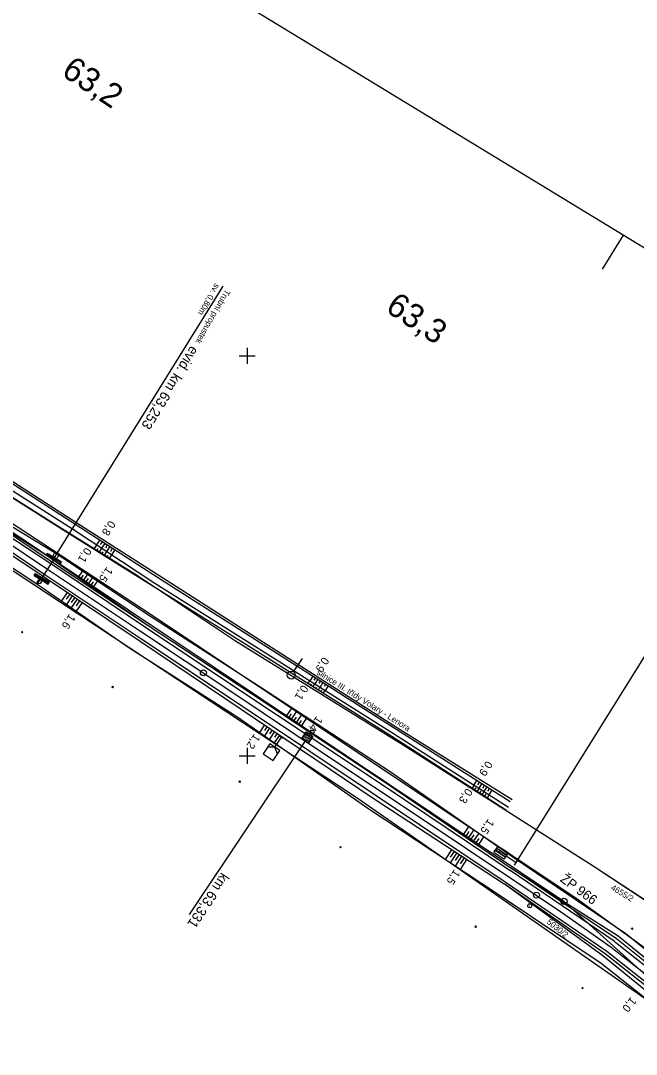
# Model space of a CAD drawing. Extents: x -804899 to -803847, y -1165742 to -1164942.
# Drawn here: x -804356.6 to -804202.8, y -1165474.6 to -1165216.2 of the extents above; entities that cross this region are included whole.
import ezdxf

# ---------------------------------------------------------------- set-up
doc = ezdxf.new("R2010")
doc.units = 0
for name, color, linetype in [('0381KM061-064P - Vrstva 1', 7, 'Continuous'), ('0381KM061-064P - Vrstva 13', 7, 'Continuous'), ('0381KM061-064P - Vrstva 17', 7, 'Continuous'), ('0381KM061-064P - Vrstva 19', 7, 'Continuous'), ('0381KM061-064P - Vrstva 27', 7, 'Continuous'), ('0381KM061-064P - Vrstva 3', 7, 'Continuous'), ('0381KM061-064P - Vrstva 36', 7, 'Continuous'), ('0381KM061-064P - Vrstva 4', 7, 'Continuous'), ('0381KM061-064P - Vrstva 48', 7, 'Continuous'), ('0381KM061-064P - Vrstva 49', 7, 'Continuous'), ('0381KM061-064P - Vrstva 51', 7, 'Continuous'), ('0381KM061-064P - Vrstva 55', 7, 'Continuous'), ('0381KM061-064P - Vrstva 57', 7, 'Continuous'), ('0381KM061-064P - Vrstva 7', 7, 'Continuous'), ('0381KM061-064P - Vrstva 8', 7, 'Continuous'), ('formát', 7, 'Continuous'), ('hran DP - hran DP', 7, 'Continuous'), ('krizky_1000 - Vrstva 1', 7, 'Continuous'), ('vyt_sit - polygon', 7, 'Continuous'), ('vyt_sit - stávající', 7, 'Continuous')]:
    doc.layers.add(name, color=color, linetype=linetype)

msp = doc.modelspace()

# ---------------------------------------------------------------- linework, layer by layer
at = {"layer": '0381KM061-064P - Vrstva 1'}
for points in [[(-804619.36, -1165173.74), (-804594.78, -1165190.05), (-804577, -1165201.91), (-804561.16, -1165212.47), (-804538.32, -1165227.67), (-804515.3, -1165243.02), (-804489.41, -1165260.27), (-804477.81, -1165268), (-804447.6, -1165288.14), (-804422.03, -1165305.2), (-804398.19, -1165321.09), (-804394.23, -1165323.73), (-804371.85, -1165338.65), (-804349.9, -1165353.29), (-804326.64, -1165368.8), (-804303.84, -1165384.01), (-804280.33, -1165399.7), (-804257.04, -1165415.23), (-804233.85, -1165430.69)], [(-804233.85, -1165430.69), (-804221.71, -1165438.86), (-804209.06, -1165447.77)], [(-804209.06, -1165447.77), (-804189.15, -1165463.4), (-804170.34, -1165480.54), (-804149.35, -1165503.13), (-804134.27, -1165522.21), (-804123.44, -1165537.79)]]:
    msp.add_lwpolyline(points, dxfattribs=at)
at = {"layer": '0381KM061-064P - Vrstva 13'}
for points in [[(-804348.53, -1165350.16), (-804348.11, -1165349.19), (-804347.55, -1165349.48)], [(-804347.71, -1165350.75), (-804347.06, -1165350.02), (-804347.55, -1165349.48)], [(-804351.94, -1165355.72), (-804352.52, -1165356.42), (-804352.55, -1165356.96)], [(-804351.23, -1165356.15), (-804351.73, -1165356.92), (-804352.55, -1165356.96)]]:
    msp.add_lwpolyline(points, dxfattribs=at)
for centre, major_axis, ratio, start_param, end_param in [((-804348.06, -1165350.36), (0.502, -0.373), 0.294364, 3.805363, 5.70381), ((-804351.59, -1165355.94), (-0.372, 0.23), 0.069899, 3.50752, 6.025727)]:
    msp.add_ellipse(centre, major_axis=major_axis, ratio=ratio, start_param=start_param, end_param=end_param, dxfattribs=at)
at = {"layer": '0381KM061-064P - Vrstva 17'}
for points in [[(-804349.85, -1165349.62), (-804346.55, -1165351.67)], [(-804349.69, -1165356.94), (-804352.99, -1165354.74)]]:
    msp.add_lwpolyline(points, dxfattribs=at)
at = {"layer": '0381KM061-064P - Vrstva 19'}
for p, q in [((-804348.23, -1165350.54), (-804306.04, -1165282.63)), ((-804348.12, -1165350.55), (-804351.58, -1165355.92))]:
    msp.add_line(p, q, dxfattribs=at)
for points in [[(-804350.13, -1165349.85), (-804349.96, -1165349.4), (-804349.94, -1165349.53)], [(-804346.52, -1165351.56), (-804349.94, -1165349.53), (-804350.13, -1165349.85), (-804346.84, -1165352.14), (-804346.52, -1165351.56)], [(-804349.96, -1165349.4), (-804348.53, -1165350.16)], [(-804346.41, -1165351.59), (-804347.71, -1165350.75)], [(-804346.84, -1165352.14), (-804346.41, -1165351.59), (-804346.52, -1165351.56)], [(-804353.14, -1165354.84), (-804353.21, -1165354.88), (-804352.95, -1165354.5)], [(-804353.14, -1165354.84), (-804349.82, -1165357.01), (-804349.52, -1165356.59), (-804352.95, -1165354.5), (-804353.14, -1165354.84)], [(-804353.21, -1165354.88), (-804351.94, -1165355.72)], [(-804349.84, -1165357.12), (-804351.23, -1165356.15)], [(-804349.52, -1165356.59), (-804349.84, -1165357.12), (-804349.82, -1165357.01)]]:
    msp.add_lwpolyline(points, dxfattribs=at)
for centre, major_axis, ratio, start_param, end_param in [((-804348.14, -1165350.46), (-0.469, 0.338), 0.066779, 5.748415, 9.878714), ((-804348.06, -1165350.36), (0.502, -0.373), 0.294364, 3.805363, 5.70381), ((-804351.59, -1165355.96), (-0.405, 0.253), 0.126448, 5.826099, 9.990944), ((-804351.59, -1165355.94), (-0.372, 0.23), 0.069899, 3.50752, 6.025727)]:
    msp.add_ellipse(centre, major_axis=major_axis, ratio=ratio, start_param=start_param, end_param=end_param, dxfattribs=at)
at = {"layer": '0381KM061-064P - Vrstva 27'}
msp.add_line((-804283.87, -1165394.04), (-804283.77, -1165394.04), dxfattribs=at)
msp.add_circle((-804283.82, -1165394.04), 0.5, dxfattribs=at)
at = {"layer": '0381KM061-064P - Vrstva 3'}
for p, q in [((-804283.6, -1165395.11), (-804286.38, -1165395.66)), ((-804284.05, -1165394.82), (-804286.08, -1165395.22)), ((-804283.9, -1165395.55), (-804285.94, -1165395.96)), ((-804284.49, -1165394.52), (-804285.79, -1165394.78)), ((-804284.93, -1165394.23), (-804285.5, -1165394.34)), ((-804284.19, -1165395.99), (-804285.5, -1165396.25)), ((-804285.55, -1165396.22), (-804314.54, -1165439.64)), ((-804284.49, -1165396.43), (-804285.06, -1165396.55))]:
    msp.add_line(p, q, dxfattribs=at)
msp.add_lwpolyline([(-804284.72, -1165396.77), (-804286.38, -1165395.66), (-804285.27, -1165394), (-804283.6, -1165395.11)], close=True, dxfattribs=at)
at = {"layer": '0381KM061-064P - Vrstva 36'}
for p, q in [((-804288.43, -1165378.96), (-804286.21, -1165375.63)), ((-804288.99, -1165379.79), (-804288.99, -1165379.79))]:
    msp.add_line(p, q, dxfattribs=at)
msp.add_circle((-804288.99, -1165379.79), 1, dxfattribs=at)
at = {"layer": '0381KM061-064P - Vrstva 4'}
for points in [[(-804755.73, -1165115.93), (-804748.17, -1165116.91), (-804721.25, -1165123.25), (-804698.66, -1165130.22), (-804681.33, -1165136.99), (-804671.47, -1165141.65), (-804648.84, -1165153.36), (-804638.11, -1165160.03), (-804624.48, -1165168.7), (-804602.56, -1165183.07), (-804574.47, -1165201.72), (-804542.72, -1165222.84), (-804507.36, -1165246.55), (-804477.08, -1165266.82), (-804448.75, -1165285.88), (-804421.18, -1165304.15), (-804392.89, -1165323.09), (-804369.85, -1165338.37), (-804348.86, -1165352.04), (-804325.13, -1165367.98), (-804299.32, -1165385.27), (-804266.05, -1165407.31), (-804234.28, -1165428.6)], [(-804755.73, -1165115.93), (-804748.03, -1165116.49), (-804721.05, -1165122.36), (-804698.44, -1165129.77), (-804680.98, -1165136.5), (-804671.21, -1165140.89), (-804648.42, -1165152.46), (-804637.55, -1165159.43), (-804624.04, -1165168.29), (-804602.25, -1165182.38), (-804573.74, -1165201.2), (-804542.46, -1165222.56), (-804507.06, -1165246.03), (-804476.47, -1165266.24), (-804448.31, -1165285.08), (-804421.02, -1165303.1), (-804392.59, -1165322.59), (-804369.41, -1165337.65), (-804348.68, -1165351.59), (-804324.76, -1165367.42), (-804298.9, -1165384.42), (-804265.65, -1165406.5), (-804234.05, -1165428.04)], [(-804626.64, -1165171.43), (-804605.18, -1165186.34), (-804576.91, -1165204.69), (-804544.69, -1165226.09), (-804509.35, -1165249.3), (-804478.87, -1165269.77), (-804450.06, -1165288.98), (-804422.82, -1165307.11), (-804394.42, -1165325.66), (-804371.77, -1165341.24), (-804350.46, -1165355.38), (-804326.73, -1165371.34), (-804301.47, -1165388.34), (-804268.3, -1165410.72), (-804235.74, -1165432.01)], [(-804576.36, -1165204.15), (-804544.19, -1165225.52), (-804508.95, -1165249), (-804478.52, -1165269.18), (-804449.67, -1165288.56), (-804422.62, -1165306.58), (-804394.22, -1165325.33), (-804371.37, -1165340.61), (-804350.54, -1165354.66), (-804326.31, -1165370.81), (-804300.9, -1165387.72), (-804267.8, -1165409.92), (-804235.52, -1165431.44)], [(-804208.29, -1165446.31), (-804234.28, -1165428.6)], [(-804207.68, -1165445.74), (-804234.05, -1165428.04)], [(-804210.55, -1165449.47), (-804235.74, -1165432.01)], [(-804235.52, -1165431.44), (-804210.13, -1165448.78)], [(-804208.29, -1165446.31), (-804188.04, -1165462.27), (-804167.24, -1165481.51), (-804148.09, -1165502.16), (-804133.09, -1165521.07), (-804122.59, -1165536.38)], [(-804149.78, -1165499.19), (-804150.31, -1165498.25), (-804166.3, -1165480.67), (-804187.69, -1165461.71), (-804207.68, -1165445.74)], [(-804153.11, -1165502.1), (-804153.8, -1165501.49), (-804170.44, -1165484.31), (-804190.7, -1165465.14), (-804210.55, -1165449.47)], [(-804210.13, -1165448.78), (-804190.15, -1165464.6), (-804169.52, -1165483.48), (-804150.26, -1165504.33), (-804135.4, -1165523.19), (-804124.45, -1165539.02), (-804124.32, -1165539.22)]]:
    msp.add_lwpolyline(points, dxfattribs=at)
at = {"layer": '0381KM061-064P - Vrstva 48'}
for p, q in [((-804337.56, -1165347.25), (-804336.79, -1165346.06)), ((-804336.62, -1165347.19), (-804336.16, -1165346.47)), ((-804336.3, -1165348.08), (-804335.53, -1165346.88)), ((-804338.21, -1165348.31), (-804337.55, -1165347.26)), ((-804337.57, -1165348.71), (-804337.25, -1165348.19)), ((-804336.93, -1165349.11), (-804336.29, -1165348.08)), ((-804336.3, -1165349.51), (-804335.98, -1165349)), ((-804335.66, -1165349.9), (-804335.04, -1165348.91)), ((-804335.36, -1165348.01), (-804334.9, -1165347.28)), ((-804335.05, -1165348.91), (-804334.27, -1165347.69)), ((-804334.11, -1165348.83), (-804333.64, -1165348.1)), ((-804333.8, -1165349.73), (-804333.01, -1165348.51)), ((-804335.03, -1165350.3), (-804334.72, -1165349.81)), ((-804334.39, -1165350.7), (-804333.79, -1165349.74)), ((-804341.15, -1165353.74), (-804342.25, -1165355.32)), ((-804340.97, -1165354.79), (-804341.63, -1165355.74)), ((-804339.9, -1165354.57), (-804341.01, -1165356.17)), ((-804339.73, -1165355.63), (-804340.4, -1165356.6)), ((-804338.66, -1165355.4), (-804339.78, -1165357.02)), ((-804338.48, -1165356.47), (-804339.16, -1165357.45)), ((-804337.41, -1165356.23), (-804338.55, -1165357.88)), ((-804346.34, -1165361.27), (-804344.9, -1165359.12)), ((-804345.15, -1165360.83), (-804344.27, -1165359.54)), ((-804345.11, -1165362.12), (-804343.65, -1165359.96)), ((-804343.91, -1165361.68), (-804343.03, -1165360.37)), ((-804343.88, -1165362.98), (-804342.41, -1165360.79)), ((-804342.67, -1165362.53), (-804341.79, -1165361.21)), ((-804342.64, -1165363.83), (-804341.16, -1165361.63)), ((-804283.59, -1165380.05), (-804284.34, -1165381.22)), ((-804282.96, -1165380.46), (-804283.33, -1165381.04)), ((-804284.75, -1165381.87), (-804284.34, -1165381.22)), ((-804284.11, -1165382.27), (-804283.91, -1165381.95)), ((-804283.48, -1165382.67), (-804283.07, -1165382.02)), ((-804282.33, -1165380.86), (-804283.07, -1165382.02)), ((-804282.85, -1165383.07), (-804282.64, -1165382.75)), ((-804282.21, -1165383.47), (-804281.81, -1165382.82)), ((-804281.7, -1165381.26), (-804282.07, -1165381.84)), ((-804281.06, -1165381.67), (-804281.8, -1165382.82)), ((-804280.43, -1165382.07), (-804280.8, -1165382.65)), ((-804279.8, -1165382.47), (-804280.54, -1165383.63)), ((-804281.58, -1165383.87), (-804281.37, -1165383.55)), ((-804280.94, -1165384.27), (-804280.54, -1165383.62)), ((-804290.26, -1165390.16), (-804288.8, -1165387.95)), ((-804289.64, -1165390.57), (-804288.9, -1165389.46)), ((-804289.01, -1165390.98), (-804287.54, -1165388.76)), ((-804288.39, -1165391.4), (-804287.65, -1165390.29)), ((-804287.76, -1165391.81), (-804286.28, -1165389.58)), ((-804286.51, -1165392.64), (-804285.02, -1165390.4)), ((-804295.65, -1165392.27), (-804296.91, -1165394.13)), ((-804294.41, -1165393.1), (-804295.68, -1165394.99)), ((-804295.03, -1165392.69), (-804295.66, -1165393.62)), ((-804293.79, -1165393.53), (-804294.43, -1165394.47)), ((-804287.14, -1165392.23), (-804286.4, -1165391.11)), ((-804293.17, -1165393.94), (-804294.45, -1165395.85)), ((-804291.92, -1165394.78), (-804293.22, -1165396.71)), ((-804292.54, -1165394.36), (-804293.19, -1165395.32)), ((-804243.31, -1165407.27), (-804242.59, -1165406.14)), ((-804243.31, -1165407.27), (-804243.8, -1165408.03)), ((-804242.88, -1165407.98), (-804243.17, -1165408.43)), ((-804242.05, -1165408.07), (-804242.54, -1165408.84)), ((-804242.39, -1165407.22), (-804241.96, -1165406.54)), ((-804242.05, -1165408.07), (-804241.33, -1165406.94)), ((-804241.61, -1165408.79), (-804241.91, -1165409.25)), ((-804240.78, -1165408.88), (-804241.29, -1165409.66)), ((-804241.13, -1165408.02), (-804240.69, -1165407.34)), ((-804240.78, -1165408.88), (-804240.06, -1165407.74)), ((-804239.86, -1165408.83), (-804239.43, -1165408.15)), ((-804239.52, -1165409.69), (-804238.8, -1165408.55)), ((-804240.35, -1165409.6), (-804240.66, -1165410.06)), ((-804239.52, -1165409.69), (-804240.03, -1165410.47)), ((-804244.59, -1165417.6), (-804246.1, -1165419.82)), ((-804244.58, -1165418.91), (-804245.48, -1165420.24)), ((-804243.36, -1165418.45), (-804244.86, -1165420.66)), ((-804242.13, -1165419.31), (-804243.62, -1165421.51)), ((-804243.34, -1165419.76), (-804244.24, -1165421.09)), ((-804242.11, -1165420.61), (-804243.01, -1165421.93)), ((-804240.9, -1165420.17), (-804242.39, -1165422.35)), ((-804250.43, -1165425.88), (-804248.84, -1165423.45)), ((-804249.18, -1165426.71), (-804247.58, -1165424.27)), ((-804249.17, -1165425.32), (-804248.21, -1165423.85)), ((-804247.93, -1165427.54), (-804246.33, -1165425.09)), ((-804247.91, -1165426.15), (-804246.95, -1165424.68)), ((-804246.68, -1165428.37), (-804245.07, -1165425.91)), ((-804246.66, -1165426.97), (-804245.7, -1165425.5))]:
    msp.add_line(p, q, dxfattribs=at)
at = {"layer": '0381KM061-064P - Vrstva 49'}
for p, q in [((-804356.09, -1165369.23), (-804356.44, -1165368.87)), ((-804356.09, -1165368.87), (-804356.44, -1165369.23)), ((-804333.45, -1165382.97), (-804333.81, -1165382.62)), ((-804333.45, -1165382.62), (-804333.81, -1165382.97)), ((-804301.7, -1165406.66), (-804302.06, -1165406.31)), ((-804301.7, -1165406.31), (-804302.06, -1165406.66)), ((-804276.5, -1165422.97), (-804276.85, -1165422.62)), ((-804276.5, -1165422.62), (-804276.85, -1165422.97)), ((-804242.71, -1165442.85), (-804243.07, -1165442.5)), ((-804242.71, -1165442.5), (-804243.07, -1165442.85)), ((-804204.05, -1165443.18), (-804203.56, -1165443.07)), ((-804203.86, -1165442.88), (-804203.75, -1165443.37)), ((-804216.05, -1165458.22), (-804216.41, -1165457.87)), ((-804216.05, -1165457.87), (-804216.41, -1165458.22))]:
    msp.add_line(p, q, dxfattribs=at)
for points in [[(-804668.09, -1165135.13), (-804646.08, -1165148.91), (-804635.34, -1165155.79), (-804621.98, -1165164.4), (-804599.68, -1165178.86), (-804570.23, -1165197.63), (-804539.04, -1165217.4), (-804503.79, -1165239.32), (-804473.21, -1165259.25), (-804445.02, -1165277.37), (-804416.3, -1165295.6), (-804385.23, -1165314.87), (-804342.84, -1165342.16), (-804322.16, -1165355.5), (-804292.15, -1165374.6), (-804262.58, -1165393.44), (-804234.25, -1165411.43)], [(-804668.53, -1165136.56), (-804646.51, -1165150.38), (-804635.75, -1165157.19), (-804622.88, -1165165.28), (-804600.74, -1165180), (-804571.06, -1165199.05), (-804539.91, -1165219.23), (-804504.85, -1165241.38), (-804474.07, -1165260.59), (-804445.75, -1165278.86), (-804417.38, -1165297.08), (-804386.13, -1165316.29), (-804343.68, -1165343.22), (-804323.05, -1165356.81), (-804293.41, -1165375.48), (-804263.45, -1165394.43), (-804234.68, -1165412.78)], [(-804576.91, -1165204.69), (-804544.69, -1165226.09), (-804509.35, -1165249.3), (-804478.87, -1165269.77), (-804450.06, -1165288.98), (-804422.82, -1165307.11), (-804394.42, -1165325.66), (-804371.77, -1165341.24), (-804350.46, -1165355.38), (-804326.73, -1165371.34), (-804301.47, -1165388.34), (-804268.3, -1165410.72), (-804235.74, -1165432.01)], [(-804474.97, -1165261.14), (-804446.16, -1165279.93), (-804417.55, -1165297.62), (-804371.56, -1165327.37), (-804344.89, -1165344.14), (-804323.3, -1165357.63), (-804293.83, -1165376.15), (-804263.84, -1165395.04), (-804235.23, -1165413.58)], [(-804475.98, -1165263.3), (-804448.01, -1165281.64), (-804419.88, -1165300.43), (-804390.2, -1165320.54), (-804368.79, -1165336.61), (-804347.55, -1165349.48), (-804323.92, -1165365.2), (-804298.45, -1165381.67), (-804264.49, -1165403.75), (-804232.5, -1165426.01)], [(-804424.02, -1165310.32), (-804397.08, -1165327.6), (-804372.3, -1165344.03), (-804352.55, -1165356.96), (-804329.59, -1165372.88)], [(-804369.41, -1165337.65), (-804350.13, -1165349.85)], [(-804348.53, -1165350.16), (-804349.96, -1165349.4), (-804350.13, -1165349.85)], [(-804348.12, -1165350.55), (-804347.55, -1165349.48)], [(-804346.84, -1165352.14), (-804346.41, -1165351.59), (-804347.71, -1165350.75)], [(-804346.84, -1165352.14), (-804324.76, -1165367.42)], [(-804351.94, -1165355.72), (-804353.21, -1165354.88), (-804352.95, -1165354.5), (-804349.52, -1165356.59), (-804349.84, -1165357.12), (-804351.23, -1165356.15)], [(-804351.58, -1165355.92), (-804352.55, -1165356.96)], [(-804324.76, -1165367.42), (-804298.9, -1165384.42), (-804265.65, -1165406.5), (-804234.05, -1165428.04)], [(-804329.59, -1165372.88), (-804302.32, -1165390.35), (-804269.85, -1165413.05), (-804237.3, -1165434.57)], [(-804232.5, -1165426.01), (-804205.4, -1165444.42), (-804185.08, -1165460.87), (-804164.82, -1165478.77), (-804146.89, -1165498.25)], [(-804234.05, -1165428.04), (-804207.28, -1165445), (-804187.24, -1165461.29), (-804165.68, -1165480.42), (-804149.47, -1165498.06), (-804149.78, -1165499.19)], [(-804211.12, -1165449.96), (-804235.74, -1165432.01)], [(-804237.3, -1165434.57), (-804211.51, -1165451.84), (-804192.43, -1165466.88), (-804171.52, -1165486.4), (-804154.9, -1165505.76)], [(-804153.11, -1165502.1), (-804154.86, -1165502.44), (-804171.26, -1165484.58), (-804191.51, -1165465.91), (-804211.12, -1165449.96)]]:
    msp.add_lwpolyline(points, dxfattribs=at)
for centre, major_axis, ratio, start_param, end_param in [((-804348.06, -1165350.36), (0.502, -0.373), 0.294364, 3.805363, 5.70381), ((-804351.59, -1165355.94), (-0.372, 0.23), 0.069899, 3.50752, 6.025727)]:
    msp.add_ellipse(centre, major_axis=major_axis, ratio=ratio, start_param=start_param, end_param=end_param, dxfattribs=at)
at = {"layer": '0381KM061-064P - Vrstva 51'}
msp.add_line((-804262.45, -1165392.96), (-804233.82, -1165410.93), dxfattribs=at)
msp.add_lwpolyline([(-804728.9, -1165105.9), (-804711.54, -1165108.67), (-804704.35, -1165111.8), (-804683.69, -1165124.09), (-804676.95, -1165128.43), (-804667.36, -1165134.41), (-804645.71, -1165148.3), (-804634.7, -1165155.23), (-804621.63, -1165163.62), (-804599.19, -1165178.23), (-804569.67, -1165197.16), (-804538.42, -1165216.77), (-804503.41, -1165238.94), (-804472.82, -1165258.55), (-804444.57, -1165276.4), (-804415.82, -1165294.73), (-804384.7, -1165314.57), (-804342.59, -1165341.72), (-804321.8, -1165355.02), (-804291.77, -1165374.22), (-804262.45, -1165392.96)], dxfattribs=at)
at = {"layer": '0381KM061-064P - Vrstva 55'}
msp.add_lwpolyline([(-804468.27, -1165264.32), (-804426.86, -1165291.43), (-804390.35, -1165315.35), (-804348.41, -1165341.86), (-804327.45, -1165354.94), (-804302.94, -1165371.26), (-804261.01, -1165397.26), (-804213.5, -1165427.44), (-804191.69, -1165441.88), (-804177.28, -1165451.4), (-804169.73, -1165458.18), (-804172.29, -1165470.42), (-804193.11, -1165453.43), (-804217.51, -1165435.77), (-804323.51, -1165365.07), (-804402.46, -1165313.29)], close=True, dxfattribs=at)
at = {"layer": '0381KM061-064P - Vrstva 7'}
for p, q in [((-804293.09, -1165397.82), (-804291.43, -1165395.33)), ((-804291.01, -1165395.61), (-804291.84, -1165395.05)), ((-804229.44, -1165437.43), (-804229.36, -1165437.49))]:
    msp.add_line(p, q, dxfattribs=at)
for points in [[(-804293.09, -1165397.82), (-804294.34, -1165396.99), (-804296, -1165399.49), (-804293.51, -1165401.15), (-804291.84, -1165398.66), (-804293.09, -1165397.82)], [(-804292.4, -1165399.49), (-804293.09, -1165397.82), (-804294.9, -1165397.82)]]:
    msp.add_lwpolyline(points, dxfattribs=at)
for centre, radius in [((-804310.94, -1165379.23), 0.75), ((-804227.7, -1165434.8), 0.75), ((-804229.4, -1165437.46), 0.5)]:
    msp.add_circle(centre, radius, dxfattribs=at)
at = {"layer": '0381KM061-064P - Vrstva 8'}
for p, q in [((-804232.81, -1165426.68), (-804194.18, -1165364.63)), ((-804236.98, -1165423.48), (-804237.94, -1165423.67)), ((-804237.42, -1165423.18), (-804237.73, -1165423.24)), ((-804236.54, -1165423.77), (-804237.5, -1165423.96)), ((-804236.09, -1165424.06), (-804237.06, -1165424.26)), ((-804235.65, -1165424.36), (-804236.62, -1165424.55)), ((-804235.21, -1165424.65), (-804236.18, -1165424.85)), ((-804235.33, -1165425.06), (-804235.74, -1165425.14)), ((-804233.22, -1165427.3), (-804232.39, -1165426.05))]:
    msp.add_line(p, q, dxfattribs=at)
for points in [[(-804235.86, -1165425.84), (-804238.35, -1165424.18), (-804237.24, -1165422.52), (-804234.75, -1165424.18), (-804235.86, -1165425.84)], [(-804235.3, -1165425.01), (-804232.81, -1165426.68)]]:
    msp.add_lwpolyline(points, dxfattribs=at)
msp.add_lwpolyline([(-804235.5, -1165425.3), (-804237.99, -1165423.64), (-804237.61, -1165423.06), (-804235.11, -1165424.72)], close=True, dxfattribs=at)
at = {"layer": 'formát'}
for p, q in [((-804206.05, -1165269.84), (-804743.98, -1164941.92)), ((-804206.05, -1165269.84), (-804211.25, -1165278.38)), ((-804026.74, -1165379.15), (-804206.05, -1165269.84))]:
    msp.add_line(p, q, dxfattribs=at)
at = {"layer": 'hran DP - hran DP'}
for p, q in [((-804390.35, -1165315.35), (-804348.41, -1165341.86)), ((-804272.3, -1165410.7), (-804413.53, -1165317.49)), ((-804348.41, -1165341.86), (-804327.45, -1165354.94)), ((-804327.45, -1165354.94), (-804302.94, -1165371.26)), ((-804302.94, -1165371.26), (-804261.01, -1165397.26)), ((-804261.01, -1165397.26), (-804213.5, -1165427.44)), ((-804199.72, -1165461.33), (-804272.3, -1165410.7)), ((-804213.5, -1165427.44), (-804191.69, -1165441.88))]:
    msp.add_line(p, q, dxfattribs=at)
at = {"layer": 'krizky_1000 - Vrstva 1'}
for points in [[(-804302, -1165300), (-804298, -1165300)], [(-804300, -1165298), (-804300, -1165302)], [(-804300, -1165398), (-804300, -1165402)], [(-804302, -1165400), (-804298, -1165400)]]:
    msp.add_lwpolyline(points, dxfattribs=at)
at = {"layer": 'vyt_sit - polygon'}
for p, q in [((-804220.83, -1165436.35), (-804399.95, -1165316.58)), ((-804145.72, -1165504.18), (-804220.83, -1165436.35))]:
    msp.add_line(p, q, dxfattribs=at)
at = {"layer": 'vyt_sit - stávající'}
msp.add_line((-804220.87, -1165436.32), (-804220.79, -1165436.38), dxfattribs=at)
msp.add_circle((-804220.83, -1165436.35), 0.756, dxfattribs=at)

# ---------------------------------------------------------------- texts
at = {"layer": '0381KM061-064P - Vrstva 19'}
for s, height, rotation, p in [('sv. 0,80m', 1.5, 240.1321, (-804308.03, -1165281.79)), ('Trubní propustek', 1.5, 240.1321, (-804305.42, -1165283.29)), ('evid. km 63,253', 2.5, 238.1402, (-804314.07, -1165297.33))]:
    msp.add_text(s, height=height, rotation=rotation, dxfattribs=at).set_placement(p)
at = {"layer": '0381KM061-064P - Vrstva 3'}
msp.add_text('km 63,331', height=2.5, rotation=236.2785, dxfattribs=at).set_placement((-804306.42, -1165428.98))
at = {"layer": '0381KM061-064P - Vrstva 48'}
for s, rotation, p in [('0,8', 237.1733, (-804334.42, -1165341.01)), ('0,1', 238.0111, (-804340.44, -1165347.75)), ('1,5', 235.3116, (-804335.06, -1165352.61)), ('1,6', 236.0582, (-804344.4, -1165364.35)), ('0,9', 237.503, (-804281.05, -1165375.12)), ('0,1', 237.7998, (-804286.25, -1165382.09)), ('1,4', 236.4166, (-804282.66, -1165389.9)), ('1,2', 236.0013, (-804298.21, -1165394.34)), ('0,9', 237.5753, (-804240.19, -1165401.08)), ('0,3', 237.0482, (-804245.18, -1165407.93)), ('1,5', 235.7229, (-804239.75, -1165415.6)), ('1,5', 236.8157, (-804248.25, -1165428.23)), ('1,0', 230.8744, (-804204.05, -1165460.12))]:
    msp.add_text(s, height=2, rotation=rotation, dxfattribs=at).set_placement(p)
at = {"layer": '0381KM061-064P - Vrstva 51'}
msp.add_text('silnice III. třídy Volary - Lenora', height=1.5, rotation=327.9008, dxfattribs=at).set_placement((-804282.76, -1165379.52))
at = {"layer": '0381KM061-064P - Vrstva 57'}
for s, rotation, p in [('4655/2', 328.8234, (-804209.28, -1165433.32)), ('5030/2', 321.7472, (-804225.31, -1165441.76))]:
    msp.add_text(s, height=1.5, rotation=rotation, dxfattribs=at).set_placement(p)
at = {"layer": '0381KM061-064P - Vrstva 7'}
for s, rotation, p in [('63,2', 326.3093, (-804346.68, -1165229.73)), ('63,3', 326.3024, (-804265.71, -1165288.72))]:
    msp.add_text(s, height=6, rotation=rotation, dxfattribs=at).set_placement(p)
at = {"layer": 'vyt_sit - stávající'}
msp.add_text('ŽP 966', height=2.4, rotation=323.5611, dxfattribs=at).set_placement((-804221.97, -1165431.19))

doc.saveas('drawing.dxf')
